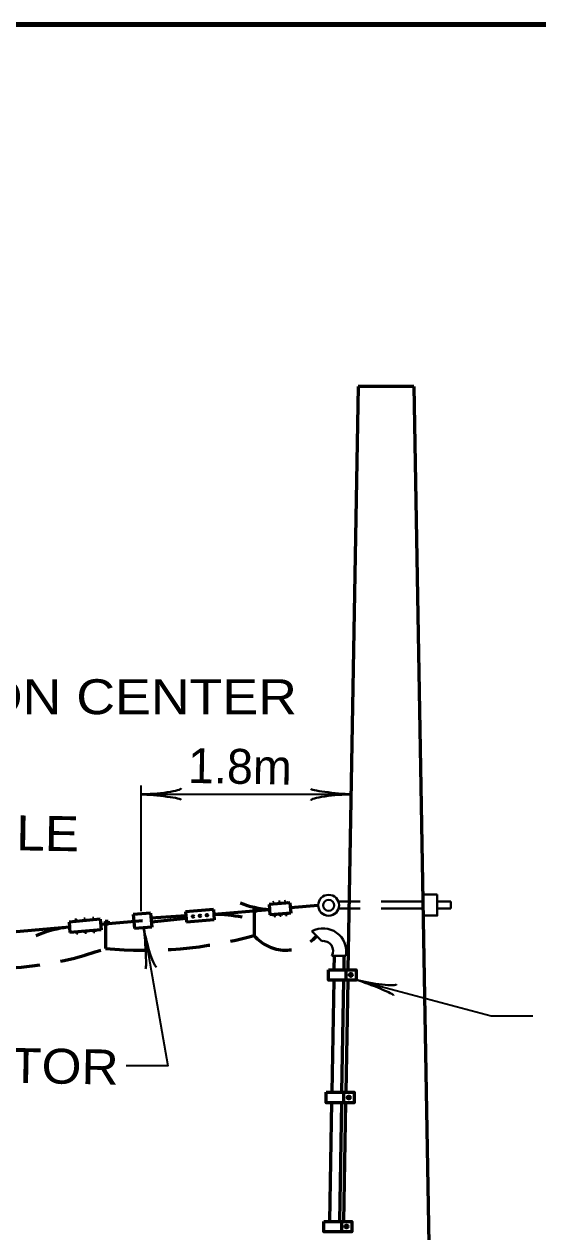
# Model space of a CAD drawing. Extents: x 14808 to 15663, y 10944 to 11488.
# Drawn here: x 15154.9 to 15199.1, y 11377.9 to 11481.7 of the extents above; entities that cross this region are included whole.
import ezdxf
from ezdxf.enums import TextEntityAlignment as Align

# ---------------------------------------------------------------- set-up
doc = ezdxf.new("R2010")
doc.units = 0
doc.header["$LTSCALE"] = 1.2
doc.linetypes.add('MEDIUM_DASHED', pattern=[4.5, 3, -1.5])
doc.layers.add('1', color=7, linetype='Continuous', lineweight=53)

msp = doc.modelspace()

# ---------------------------------------------------------------- linework, layer by layer
at = {"layer": '1'}
for p, q in [((15183.638, 11450.597), (15182.763, 11400.454)), ((15188.438, 11450.597), (15183.638, 11450.597)), ((15188.438, 11450.597), (15191.474, 11276.623)), ((15176.423, 11406.216), (15176.303, 11406.205)), ((15176.414, 11406.215), (15176.425, 11406.095)), ((15176.423, 11406.216), (15176.433, 11406.096)), ((15176.925, 11406.26), (15176.805, 11406.249)), ((15176.805, 11406.249), (15176.816, 11406.13)), ((15176.809, 11406.249), (15176.819, 11406.13)), ((15176.82, 11406.25), (15176.83, 11406.131)), ((15176.829, 11406.251), (15176.839, 11406.132)), ((15176.838, 11406.252), (15176.848, 11406.132)), ((15176.849, 11406.253), (15176.859, 11406.133)), ((15176.851, 11406.253), (15176.862, 11406.134)), ((15176.861, 11406.254), (15176.871, 11406.134)), ((15176.865, 11406.254), (15176.876, 11406.135)), ((15176.87, 11406.255), (15176.88, 11406.135)), ((15176.877, 11406.255), (15176.887, 11406.136)), ((15176.881, 11406.256), (15176.892, 11406.136)), ((15176.888, 11406.256), (15176.898, 11406.137)), ((15176.897, 11406.257), (15176.908, 11406.138)), ((15176.902, 11406.257), (15176.912, 11406.138)), ((15176.904, 11406.258), (15176.914, 11406.138)), ((15176.906, 11406.258), (15176.917, 11406.138)), ((15176.917, 11406.259), (15176.927, 11406.139)), ((15176.925, 11406.26), (15176.935, 11406.14)), ((15177.427, 11406.303), (15177.308, 11406.293)), ((15177.308, 11406.293), (15177.318, 11406.174)), ((15177.313, 11406.293), (15177.323, 11406.174)), ((15177.324, 11406.294), (15177.334, 11406.175)), ((15177.333, 11406.295), (15177.343, 11406.176)), ((15177.344, 11406.296), (15177.355, 11406.177)), ((15177.344, 11406.296), (15177.355, 11406.177)), ((15177.351, 11406.297), (15177.362, 11406.177)), ((15177.358, 11406.297), (15177.368, 11406.178)), ((15177.36, 11406.298), (15177.371, 11406.178)), ((15177.367, 11406.298), (15177.377, 11406.179)), ((15177.376, 11406.299), (15177.386, 11406.18)), ((15177.383, 11406.3), (15177.394, 11406.18)), ((15177.395, 11406.301), (15177.405, 11406.181)), ((15177.399, 11406.301), (15177.41, 11406.182)), ((15177.406, 11406.302), (15177.417, 11406.182)), ((15177.411, 11406.302), (15177.421, 11406.183)), ((15177.418, 11406.303), (15177.428, 11406.183)), ((15177.427, 11406.303), (15177.438, 11406.184)), ((15165.793, 11405.314), (15164.298, 11405.183)), ((15164.298, 11405.183), (15164.403, 11403.988)), ((15165.793, 11405.314), (15165.897, 11404.119)), ((15171.197, 11405.638), (15168.807, 11405.429)), ((15168.807, 11405.429), (15168.885, 11404.532)), ((15171.197, 11405.638), (15171.276, 11404.742)), ((15176.018, 11405.608), (15171.237, 11405.19)), ((15174.674, 11405.735), (15174.914, 11405.755)), ((15174.674, 11405.735), (15174.695, 11405.495)), ((15174.68, 11405.675), (15174.859, 11405.69)), ((15174.68, 11405.675), (15174.695, 11405.495)), ((15174.691, 11405.736), (15174.711, 11405.497)), ((15174.695, 11405.495), (15174.934, 11405.516)), ((15174.695, 11405.495), (15174.874, 11405.511)), ((15174.695, 11405.495), (15174.695, 11403.395)), ((15174.696, 11405.676), (15174.711, 11405.497)), ((15174.709, 11405.738), (15174.73, 11405.498)), ((15174.714, 11405.678), (15174.73, 11405.498)), ((15174.727, 11405.739), (15174.748, 11405.5)), ((15174.732, 11405.679), (15174.748, 11405.5)), ((15174.745, 11405.741), (15174.766, 11405.502)), ((15174.75, 11405.681), (15174.766, 11405.502)), ((15174.754, 11405.742), (15174.775, 11405.502)), ((15174.767, 11405.743), (15174.788, 11405.504)), ((15174.772, 11405.683), (15174.788, 11405.504)), ((15174.781, 11405.744), (15174.802, 11405.505)), ((15174.786, 11405.684), (15174.802, 11405.505)), ((15174.794, 11405.745), (15174.815, 11405.506)), ((15174.804, 11405.746), (15174.825, 11405.507)), ((15174.809, 11405.686), (15174.825, 11405.507)), ((15174.822, 11405.747), (15174.843, 11405.508)), ((15174.827, 11405.688), (15174.843, 11405.508)), ((15174.84, 11405.749), (15174.86, 11405.51)), ((15174.845, 11405.689), (15174.86, 11405.51)), ((15174.854, 11405.75), (15174.874, 11405.511)), ((15174.859, 11405.69), (15174.874, 11405.511)), ((15174.867, 11405.751), (15174.888, 11405.512)), ((15174.878, 11405.752), (15174.899, 11405.513)), ((15174.89, 11405.753), (15174.911, 11405.514)), ((15174.902, 11405.754), (15174.923, 11405.515)), ((15174.914, 11405.755), (15174.934, 11405.516)), ((15177.772, 11406.213), (15175.979, 11406.056)), ((15175.979, 11406.056), (15176.058, 11405.16)), ((15177.851, 11405.317), (15176.058, 11405.16)), ((15176.303, 11406.205), (15176.314, 11406.086)), ((15176.313, 11406.206), (15176.324, 11406.086)), ((15176.316, 11406.206), (15176.326, 11406.087)), ((15176.323, 11406.207), (15176.333, 11406.087)), ((15176.332, 11406.208), (15176.342, 11406.088)), ((15176.338, 11406.208), (15176.349, 11406.089)), ((15176.341, 11406.208), (15176.351, 11406.089)), ((15176.347, 11406.209), (15176.358, 11406.09)), ((15176.354, 11406.21), (15176.364, 11406.09)), ((15176.359, 11406.21), (15176.369, 11406.091)), ((15176.37, 11406.211), (15176.38, 11406.091)), ((15176.379, 11406.212), (15176.389, 11406.092)), ((15176.39, 11406.213), (15176.4, 11406.093)), ((15176.392, 11406.213), (15176.403, 11406.093)), ((15176.392, 11405.189), (15176.403, 11405.068)), ((15176.394, 11406.213), (15176.405, 11406.094)), ((15176.397, 11406.213), (15176.407, 11406.094)), ((15176.401, 11406.214), (15176.411, 11406.094)), ((15176.404, 11405.19), (15176.414, 11405.069)), ((15176.408, 11405.191), (15176.419, 11405.07)), ((15176.41, 11406.214), (15176.42, 11406.095)), ((15176.415, 11405.191), (15176.425, 11405.07)), ((15176.422, 11405.192), (15176.432, 11405.071)), ((15176.43, 11405.192), (15176.441, 11405.072)), ((15176.441, 11405.193), (15176.452, 11405.073)), ((15176.45, 11405.194), (15176.461, 11405.073)), ((15176.457, 11405.195), (15176.468, 11405.074)), ((15176.466, 11405.196), (15176.476, 11405.075)), ((15176.475, 11405.196), (15176.485, 11405.076)), ((15176.486, 11405.197), (15176.497, 11405.077)), ((15176.488, 11405.198), (15176.499, 11405.077)), ((15176.49, 11405.198), (15176.501, 11405.077)), ((15176.5, 11405.199), (15176.511, 11405.078)), ((15176.512, 11405.2), (15176.523, 11405.079)), ((15176.894, 11405.233), (15176.905, 11405.112)), ((15176.899, 11405.233), (15176.91, 11405.113)), ((15176.908, 11405.234), (15176.919, 11405.113)), ((15176.915, 11405.235), (15176.926, 11405.114)), ((15176.926, 11405.236), (15176.937, 11405.115)), ((15176.929, 11405.236), (15176.939, 11405.115)), ((15176.944, 11405.237), (15176.955, 11405.117)), ((15176.954, 11405.238), (15176.965, 11405.118)), ((15176.971, 11405.24), (15176.982, 11405.119)), ((15176.98, 11405.24), (15176.991, 11405.12)), ((15176.987, 11405.241), (15176.997, 11405.12)), ((15176.996, 11405.242), (15177.006, 11405.121)), ((15177.007, 11405.243), (15177.017, 11405.122)), ((15177.014, 11405.244), (15177.025, 11405.123)), ((15177.397, 11405.277), (15177.407, 11405.156)), ((15177.407, 11405.278), (15177.417, 11405.157)), ((15177.413, 11405.278), (15177.423, 11405.158)), ((15177.417, 11405.279), (15177.428, 11405.158)), ((15177.422, 11405.279), (15177.433, 11405.158)), ((15177.422, 11405.279), (15177.432, 11405.158)), ((15177.431, 11405.28), (15177.442, 11405.159)), ((15177.438, 11405.281), (15177.448, 11405.16)), ((15177.445, 11405.281), (15177.455, 11405.16)), ((15177.453, 11405.282), (15177.464, 11405.161)), ((15177.458, 11405.282), (15177.469, 11405.162)), ((15177.465, 11405.283), (15177.476, 11405.162)), ((15177.472, 11405.284), (15177.482, 11405.163)), ((15177.481, 11405.284), (15177.491, 11405.164)), ((15177.488, 11405.285), (15177.498, 11405.164)), ((15177.497, 11405.286), (15177.508, 11405.165)), ((15177.497, 11405.286), (15177.507, 11405.165)), ((15177.502, 11405.286), (15177.512, 11405.165)), ((15177.508, 11405.287), (15177.519, 11405.166)), ((15177.516, 11405.288), (15177.527, 11405.167)), ((15177.772, 11406.213), (15177.851, 11405.317)), ((15180.202, 11405.974), (15177.812, 11405.765)), ((15161.472, 11404.786), (15158.783, 11404.55)), ((15158.783, 11404.55), (15158.861, 11403.654)), ((15159.444, 11404.732), (15159.325, 11404.721)), ((15159.335, 11404.599), (15159.325, 11404.721)), ((15159.336, 11404.599), (15159.325, 11404.721)), ((15159.338, 11404.599), (15159.328, 11404.721)), ((15159.349, 11404.6), (15159.338, 11404.722)), ((15159.351, 11404.6), (15159.341, 11404.723)), ((15159.351, 11404.6), (15159.341, 11404.723)), ((15159.362, 11404.601), (15159.352, 11404.724)), ((15159.365, 11404.601), (15159.354, 11404.724)), ((15159.365, 11404.601), (15159.354, 11404.724)), ((15159.372, 11404.602), (15159.361, 11404.724)), ((15159.371, 11404.602), (15159.361, 11404.724)), ((15159.38, 11404.603), (15159.37, 11404.725)), ((15159.392, 11404.604), (15159.381, 11404.726)), ((15159.394, 11404.604), (15159.383, 11404.726)), ((15159.4, 11404.604), (15159.39, 11404.727)), ((15159.409, 11404.605), (15159.399, 11404.728)), ((15159.418, 11404.606), (15159.407, 11404.729)), ((15159.418, 11404.606), (15159.407, 11404.729)), ((15159.425, 11404.606), (15159.415, 11404.729)), ((15159.432, 11404.607), (15159.421, 11404.73)), ((15159.436, 11404.608), (15159.425, 11404.73)), ((15159.436, 11404.608), (15159.426, 11404.73)), ((15159.445, 11404.608), (15159.434, 11404.731)), ((15159.45, 11404.609), (15159.439, 11404.731)), ((15159.455, 11404.609), (15159.444, 11404.732)), ((15160.177, 11404.795), (15160.057, 11404.785)), ((15160.068, 11404.663), (15160.057, 11404.785)), ((15160.075, 11404.663), (15160.065, 11404.786)), ((15160.08, 11404.664), (15160.069, 11404.786)), ((15160.084, 11404.664), (15160.074, 11404.786)), ((15160.093, 11404.665), (15160.082, 11404.787)), ((15160.097, 11404.665), (15160.087, 11404.788)), ((15160.1, 11404.666), (15160.089, 11404.788)), ((15160.109, 11404.666), (15160.098, 11404.789)), ((15160.118, 11404.667), (15160.107, 11404.789)), ((15160.118, 11404.667), (15160.107, 11404.789)), ((15160.118, 11404.667), (15160.107, 11404.789)), ((15160.122, 11404.668), (15160.111, 11404.79)), ((15160.127, 11404.668), (15160.117, 11404.79)), ((15160.129, 11404.668), (15160.118, 11404.79)), ((15160.133, 11404.668), (15160.123, 11404.791)), ((15160.142, 11404.669), (15160.131, 11404.792)), ((15160.142, 11404.669), (15160.131, 11404.792)), ((15160.147, 11404.67), (15160.136, 11404.792)), ((15160.149, 11404.67), (15160.138, 11404.792)), ((15160.151, 11404.67), (15160.14, 11404.792)), ((15160.151, 11404.67), (15160.14, 11404.792)), ((15160.155, 11404.67), (15160.145, 11404.793)), ((15160.158, 11404.671), (15160.147, 11404.793)), ((15160.165, 11404.671), (15160.154, 11404.793)), ((15160.169, 11404.672), (15160.158, 11404.794)), ((15160.173, 11404.672), (15160.163, 11404.794)), ((15160.176, 11404.672), (15160.165, 11404.794)), ((15160.18, 11404.673), (15160.169, 11404.795)), ((15160.187, 11404.673), (15160.177, 11404.795)), ((15160.91, 11404.849), (15160.79, 11404.839)), ((15160.8, 11404.727), (15160.79, 11404.839)), ((15160.81, 11404.728), (15160.8, 11404.84)), ((15160.812, 11404.728), (15160.802, 11404.84)), ((15160.814, 11404.728), (15160.805, 11404.84)), ((15160.823, 11404.729), (15160.813, 11404.841)), ((15160.825, 11404.729), (15160.816, 11404.841)), ((15160.828, 11404.729), (15160.818, 11404.841)), ((15160.835, 11404.73), (15160.825, 11404.842)), ((15160.843, 11404.731), (15160.833, 11404.843)), ((15160.846, 11404.731), (15160.836, 11404.843)), ((15160.855, 11404.732), (15160.845, 11404.844)), ((15160.861, 11404.732), (15160.851, 11404.844)), ((15160.868, 11404.733), (15160.858, 11404.845)), ((15160.873, 11404.733), (15160.863, 11404.845)), ((15160.879, 11404.734), (15160.87, 11404.846)), ((15160.889, 11404.735), (15160.879, 11404.846)), ((15160.893, 11404.735), (15160.883, 11404.847)), ((15160.9, 11404.736), (15160.89, 11404.847)), ((15160.909, 11404.736), (15160.899, 11404.848)), ((15160.915, 11404.737), (15160.905, 11404.849)), ((15160.919, 11404.737), (15160.91, 11404.849)), ((15161.472, 11404.786), (15161.551, 11403.889)), ((15165.098, 11404.651), (15161.511, 11404.337)), ((15161.904, 11404.615), (15162.143, 11404.636)), ((15161.904, 11404.615), (15161.925, 11404.376)), ((15161.909, 11404.555), (15162.089, 11404.57)), ((15161.909, 11404.555), (15161.925, 11404.376)), ((15161.92, 11404.616), (15161.941, 11404.377)), ((15161.925, 11404.376), (15162.164, 11404.396)), ((15161.925, 11404.376), (15162.104, 11404.391)), ((15161.925, 11404.376), (15161.925, 11402.275)), ((15161.926, 11404.556), (15161.941, 11404.377)), ((15161.939, 11404.618), (15161.959, 11404.379)), ((15161.944, 11404.558), (15161.959, 11404.379)), ((15161.957, 11404.619), (15161.978, 11404.38)), ((15161.962, 11404.559), (15161.978, 11404.38)), ((15161.975, 11404.621), (15161.996, 11404.382)), ((15161.98, 11404.561), (15161.996, 11404.382)), ((15161.984, 11404.622), (15162.005, 11404.383)), ((15161.997, 11404.623), (15162.018, 11404.384)), ((15162.002, 11404.563), (15162.018, 11404.384)), ((15162.011, 11404.624), (15162.031, 11404.385)), ((15162.016, 11404.564), (15162.031, 11404.385)), ((15162.024, 11404.625), (15162.044, 11404.386)), ((15162.034, 11404.626), (15162.054, 11404.387)), ((15162.039, 11404.566), (15162.054, 11404.387)), ((15162.052, 11404.628), (15162.072, 11404.388)), ((15162.057, 11404.568), (15162.072, 11404.388)), ((15162.069, 11404.629), (15162.09, 11404.39)), ((15162.075, 11404.569), (15162.09, 11404.39)), ((15162.084, 11404.63), (15162.104, 11404.391)), ((15162.089, 11404.57), (15162.104, 11404.391)), ((15162.097, 11404.631), (15162.117, 11404.392)), ((15162.108, 11404.632), (15162.129, 11404.393)), ((15162.12, 11404.633), (15162.141, 11404.394)), ((15162.132, 11404.635), (15162.153, 11404.395)), ((15162.143, 11404.636), (15162.164, 11404.396)), ((15168.836, 11405.096), (15165.83, 11404.886)), ((15168.856, 11404.861), (15165.86, 11404.546)), ((15171.276, 11404.742), (15168.885, 11404.532)), ((15176.523, 11405.079), (15176.403, 11405.068)), ((15177.025, 11405.123), (15176.905, 11405.112)), ((15177.527, 11405.167), (15177.407, 11405.156)), ((15158.822, 11404.102), (15074.187, 11396.698)), ((15160.206, 11403.771), (15158.861, 11403.654)), ((15159.424, 11403.583), (15159.414, 11403.702)), ((15159.432, 11403.583), (15159.422, 11403.703)), ((15159.544, 11403.593), (15159.424, 11403.583)), ((15159.443, 11403.584), (15159.433, 11403.704)), ((15159.45, 11403.585), (15159.439, 11403.704)), ((15159.454, 11403.585), (15159.444, 11403.705)), ((15159.456, 11403.585), (15159.446, 11403.705)), ((15159.459, 11403.586), (15159.448, 11403.705)), ((15159.465, 11403.586), (15159.455, 11403.706)), ((15159.465, 11403.586), (15159.455, 11403.706)), ((15159.477, 11403.587), (15159.466, 11403.707)), ((15159.483, 11403.588), (15159.473, 11403.707)), ((15159.486, 11403.588), (15159.475, 11403.707)), ((15159.49, 11403.588), (15159.48, 11403.708)), ((15159.49, 11403.588), (15159.48, 11403.708)), ((15159.501, 11403.589), (15159.491, 11403.709)), ((15159.51, 11403.59), (15159.5, 11403.71)), ((15159.517, 11403.591), (15159.506, 11403.71)), ((15159.519, 11403.591), (15159.509, 11403.71)), ((15159.521, 11403.591), (15159.511, 11403.711)), ((15159.524, 11403.591), (15159.513, 11403.711)), ((15159.528, 11403.592), (15159.517, 11403.711)), ((15159.532, 11403.592), (15159.522, 11403.712)), ((15159.535, 11403.592), (15159.524, 11403.712)), ((15159.544, 11403.593), (15159.533, 11403.713)), ((15160.156, 11403.647), (15160.146, 11403.766)), ((15160.161, 11403.647), (15160.15, 11403.766)), ((15160.276, 11403.657), (15160.156, 11403.647)), ((15160.17, 11403.648), (15160.16, 11403.767)), ((15160.17, 11403.648), (15160.16, 11403.767)), ((15160.172, 11403.648), (15160.162, 11403.767)), ((15160.183, 11403.649), (15160.173, 11403.768)), ((15160.188, 11403.649), (15160.178, 11403.769)), ((15160.197, 11403.65), (15160.186, 11403.77)), ((15160.199, 11403.65), (15160.189, 11403.77)), ((15160.209, 11403.651), (15160.198, 11403.771)), ((15160.213, 11403.651), (15160.202, 11403.771)), ((15161.551, 11403.889), (15160.206, 11403.771)), ((15160.216, 11403.652), (15160.206, 11403.771)), ((15160.221, 11403.652), (15160.211, 11403.772)), ((15160.221, 11403.652), (15160.211, 11403.772)), ((15160.231, 11403.653), (15160.22, 11403.773)), ((15160.239, 11403.654), (15160.229, 11403.773)), ((15160.244, 11403.654), (15160.233, 11403.774)), ((15160.251, 11403.655), (15160.24, 11403.774)), ((15160.257, 11403.655), (15160.247, 11403.775)), ((15160.257, 11403.655), (15160.247, 11403.775)), ((15160.268, 11403.656), (15160.258, 11403.776)), ((15160.276, 11403.657), (15160.266, 11403.776)), ((15160.889, 11403.711), (15160.878, 11403.83)), ((15160.894, 11403.711), (15160.884, 11403.831)), ((15160.898, 11403.712), (15160.888, 11403.831)), ((15161.008, 11403.721), (15160.889, 11403.711)), ((15160.91, 11403.713), (15160.899, 11403.832)), ((15160.921, 11403.713), (15160.911, 11403.833)), ((15160.928, 11403.714), (15160.918, 11403.834)), ((15160.937, 11403.715), (15160.927, 11403.834)), ((15160.945, 11403.716), (15160.934, 11403.835)), ((15160.95, 11403.716), (15160.94, 11403.836)), ((15160.954, 11403.716), (15160.943, 11403.836)), ((15160.964, 11403.717), (15160.953, 11403.837)), ((15160.964, 11403.717), (15160.953, 11403.837)), ((15160.972, 11403.718), (15160.962, 11403.838)), ((15160.975, 11403.718), (15160.964, 11403.838)), ((15160.986, 11403.719), (15160.975, 11403.839)), ((15160.986, 11403.719), (15160.975, 11403.839)), ((15160.995, 11403.72), (15160.984, 11403.839)), ((15161.004, 11403.721), (15160.994, 11403.84)), ((15161.008, 11403.721), (15160.998, 11403.841)), ((15165.897, 11404.119), (15164.403, 11403.988)), ((15181.581, 11401.656), (15181.56, 11400.455)), ((15182.421, 11401.656), (15182.4, 11400.437)), ((15182.583, 11400.446), (15182.583, 11399.546)), ((15181.545, 11399.545), (15181.377, 11389.929)), ((15182.384, 11399.535), (15182.217, 11389.929)), ((15182.746, 11399.526), (15182.579, 11389.93)), ((15182.393, 11389.919), (15182.393, 11389.02)), ((15181.361, 11389.028), (15181.183, 11378.822)), ((15182.201, 11389.01), (15182.023, 11378.822)), ((15182.563, 11389.019), (15182.385, 11378.818)), ((15182.199, 11378.818), (15182.199, 11377.918))]:
    msp.add_line(p, q, dxfattribs=at)
at = {"layer": '1', "lineweight": 35}
for p, q in [((15164.975, 11405.497), (15164.975, 11416.297)), ((15164.975, 11415.53), (15183.026, 11415.53))]:
    msp.add_line(p, q, dxfattribs=at)
at = {"layer": '1', "linetype": 'MEDIUM_DASHED', "lineweight": 40}
for p, q in [((15189.214, 11406.304), (15181.964, 11406.304)), ((15189.214, 11405.704), (15181.964, 11405.704))]:
    msp.add_line(p, q, dxfattribs=at)
at = {"layer": '1', "lineweight": 40}
for p, q in [((15190.433, 11406.904), (15189.225, 11406.904)), ((15190.433, 11406.304), (15191.614, 11406.304)), ((15191.614, 11405.704), (15191.614, 11406.304)), ((15190.433, 11405.704), (15191.614, 11405.704)), ((15179.668, 11403.759), (15180.517, 11402.91)), ((15181.382, 11401.656), (15182.582, 11401.656))]:
    msp.add_line(p, q, dxfattribs=at)
at = {"layer": '1', "lineweight": 25}
for p, q in [((15171.237, 11405.19), (15171.478, 11405.211)), ((15177.812, 11405.765), (15178.105, 11405.791)), ((15161.511, 11404.337), (15161.981, 11404.378)), ((15158.822, 11404.102), (15158.365, 11404.062))]:
    msp.add_line(p, q, dxfattribs=at)
at = {"layer": '1', "lineweight": 158}
msp.add_lwpolyline([(15656.868, 11481.74), (14865.168, 11481.64), (14865.268, 10955.64)], dxfattribs=at)
at = {"layer": '1', "lineweight": 40}
msp.add_lwpolyline([(15190.433, 11406.904), (15190.433, 11405.104), (15189.229, 11405.104)], dxfattribs=at)
at = {"layer": '1', "lineweight": 35}
for points in [[(15165.207, 11403.993), (15167.291, 11392.175), (15163.691, 11392.175)], [(15183.473, 11399.586), (15195.064, 11396.48), (15198.664, 11396.48)]]:
    msp.add_lwpolyline(points, dxfattribs=at)
at = {"layer": '1'}
for points in [[(15181.083, 11400.446), (15183.483, 11400.446), (15183.483, 11399.546), (15181.083, 11399.546)], [(15180.893, 11389.919), (15183.293, 11389.919), (15183.293, 11389.02), (15180.893, 11389.02)], [(15180.699, 11378.818), (15183.099, 11378.818), (15183.099, 11377.918), (15180.699, 11377.918)]]:
    msp.add_lwpolyline(points, close=True, dxfattribs=at)
at = {"layer": '1', "lineweight": 40}
for centre, radius in [((15181.104, 11405.987), 0.9), ((15181.108, 11405.985), 0.472)]:
    msp.add_circle(centre, radius, dxfattribs=at)
at = {"layer": '1'}
for centre, radius in [((15170.642, 11405.137), 0.06), ((15169.446, 11405.035), 0.06), ((15170.044, 11405.088), 0.06), ((15183.019, 11400), 0.12), ((15182.829, 11389.473), 0.12), ((15182.635, 11378.372), 0.12)]:
    msp.add_circle(centre, radius, dxfattribs=at)
for centre, start, end in [((15171.454, 11394.762), 77.79454, 91.19453), ((15177.073, 11415.985), 249.94661, 264.19453), ((15159.962, 11393.755), 98.80547, 112.81313)]:
    msp.add_arc(centre, 10.43, start, end, dxfattribs=at)
at = {"layer": '1', "linetype": 'MEDIUM_DASHED'}
for centre, radius, start, end in [((15165.26, 11437.623), 35.504, 264.61066, 285.41207), ((15177.401, 11405.668), 3.533, 220.02355, 318.67214), ((15152.21, 11429.158), 28.584, 260.14661, 289.87015)]:
    msp.add_arc(centre, radius, start, end, dxfattribs=at)
at = {"layer": '1', "lineweight": 40}
for centre, radius, start, end in [((15180.628, 11402.018), 1.988, 349.50124, 118.8707), ((15180.64, 11402.069), 0.85, 330.86779, 98.35179)]:
    msp.add_arc(centre, radius, start, end, dxfattribs=at)
for centre, major_axis, ratio, start_param, end_param in [((15166.285, 11415.861), (-2.143, -0.187), 0.122415, 0.8963533, 3.1415927), ((15181.681, 11415.784), (2.108, -0.211), 0.07063, 3.1407148, 5.41811), ((15166.32, 11415.276), (2.108, -0.211), 0.07063, 6.2823074, 8.5597026), ((15181.716, 11415.198), (2.143, 0.187), 0.122415, 0.8963533, 3.1415927), ((15165.19, 11402.624), (-0.158, 2.112), 0.07063, 3.1407148, 5.41811), ((15165.761, 11402.761), (-0.557, 2.078), 0.122415, 0.8963533, 3.1415927), ((15184.706, 11398.993), (1.981, -0.749), 0.07063, 6.2823074, 8.5597026), ((15184.824, 11399.568), (-2.118, 0.374), 0.122415, 0.8963533, 3.1415927)]:
    msp.add_ellipse(centre, major_axis=major_axis, ratio=ratio, start_param=start_param, end_param=end_param, dxfattribs=at)

# ---------------------------------------------------------------- texts
at = {"layer": '1', "width": 1.15}
msp.add_text('CABLE RINGS 15" ON CENTER', height=3, dxfattribs=at).set_placement((15110.853, 11422.418))
at = {"layer": '1'}
msp.add_text('1.8m', height=3, rotation=359, dxfattribs=at).set_placement((15173.452, 11416.433), align=Align.CENTER)
at = {"layer": '1', "width": 1.1}
msp.add_text('MESSENGER CABLE', height=3, rotation=359, dxfattribs=at).set_placement((15115.733, 11411.392))
msp.add_text('STRAIN INSULATOR', height=3, rotation=359, dxfattribs=at).set_placement((15163.022, 11390.566), align=Align.RIGHT)

doc.saveas('drawing.dxf')
